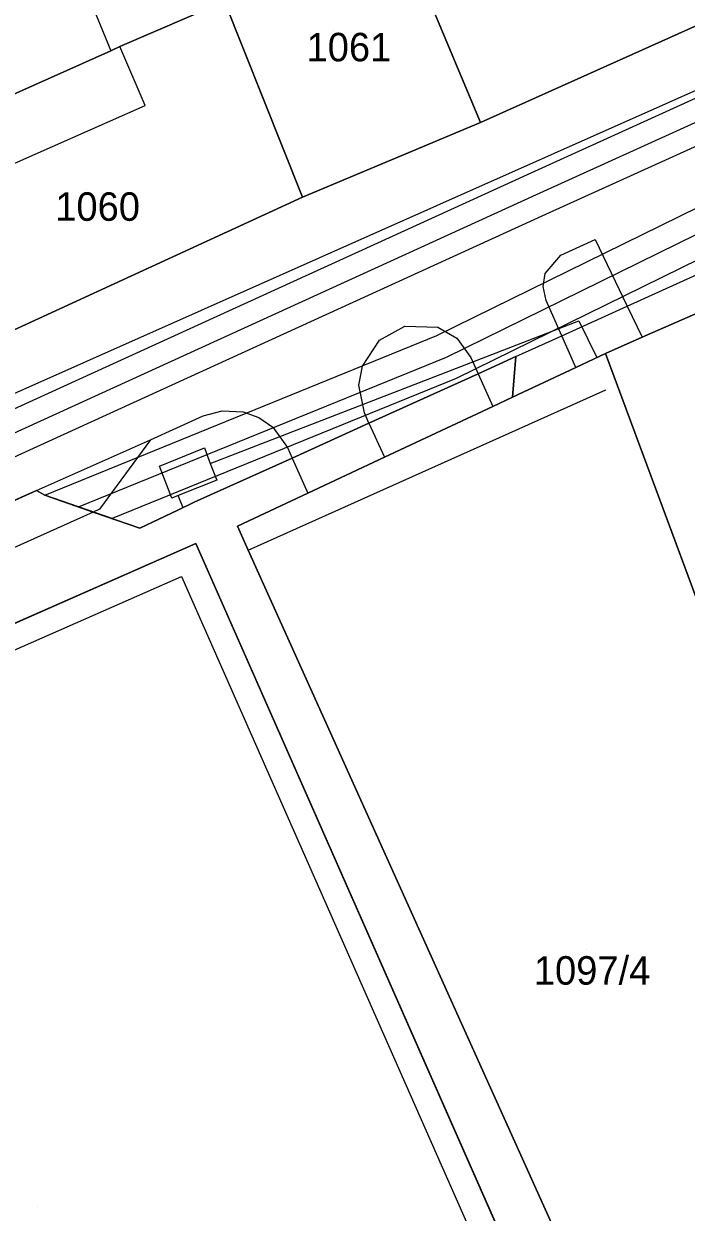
# Model space of a CAD drawing. Extents: x -263423 to -261326, y -1240067 to -1237864.
# Drawn here: x -262627.1 to -262580.6, y -1239899.5 to -1239816.1 of the extents above; entities that cross this region are included whole.
import ezdxf

# ---------------------------------------------------------------- set-up
doc = ezdxf.new("R2010")
doc.units = 0
for name, color, linetype in [('body_kn', 7, 'Continuous'), ('kladpar_druhypozemkov', 7, 'Continuous'), ('kladpar_hranice', 7, 'Continuous'), ('kladpar_parcelnecisla', 7, 'Continuous'), ('kladpar_plochy', 7, 'Continuous'), ('linie', 7, 'Continuous'), ('tarchy_linie', 7, 'Continuous'), ('zappar_hrandruhpozemk', 7, 'Continuous')]:
    doc.layers.add(name, color=color, linetype=linetype)

msp = doc.modelspace()

# ---------------------------------------------------------------- linework, layer by layer
at = {"layer": 'body_kn'}
for p, q in [((-262620.98, -1239817.98), (-262620.98, -1239817.98)), ((-262620.34, -1239817.67), (-262620.34, -1239817.67)), ((-262618.57, -1239821.82), (-262618.57, -1239821.82)), ((-262595.03, -1239823), (-262595.03, -1239823)), ((-262591.74, -1239826.65), (-262591.74, -1239826.65)), ((-262607.52, -1239828.24), (-262607.52, -1239828.24)), ((-262591.1, -1239828.06), (-262591.1, -1239828.06)), ((-262590.46, -1239829.47), (-262590.46, -1239829.47)), ((-262586.98, -1239831.23), (-262586.98, -1239831.23)), ((-262589.38, -1239832.33), (-262589.38, -1239832.33)), ((-262590.5, -1239833.61), (-262590.5, -1239833.61)), ((-262590.64, -1239834.52), (-262590.64, -1239834.52)), ((-262590.43, -1239835.51), (-262590.43, -1239835.51)), ((-262584.73, -1239835.9), (-262584.73, -1239835.9)), ((-262600.35, -1239837.31), (-262600.35, -1239837.31)), ((-262598.02, -1239837.38), (-262598.02, -1239837.38)), ((-262588.12, -1239836.94), (-262588.12, -1239836.94)), ((-262598.1, -1239837.97), (-262598.1, -1239837.97)), ((-262596.69, -1239838.16), (-262596.69, -1239838.16)), ((-262589.32, -1239837.99), (-262589.32, -1239837.99)), ((-262583.68, -1239838.09), (-262583.68, -1239838.09)), ((-262602.12, -1239838.3), (-262602.12, -1239838.3)), ((-262597.42, -1239839.48), (-262597.42, -1239839.48)), ((-262595.7, -1239839.5), (-262595.7, -1239839.5)), ((-262592.55, -1239839.45), (-262592.55, -1239839.45)), ((-262592.55, -1239839.45), (-262592.55, -1239839.45)), ((-262586.86, -1239839.51), (-262586.86, -1239839.51)), ((-262586.25, -1239839.22), (-262586.25, -1239839.22)), ((-262603.31, -1239840.11), (-262603.31, -1239840.11)), ((-262595.19, -1239840.65), (-262595.19, -1239840.65)), ((-262588.33, -1239840.2), (-262588.33, -1239840.2)), ((-262603.56, -1239841.45), (-262603.56, -1239841.45)), ((-262596.74, -1239840.99), (-262596.74, -1239840.99)), ((-262592.79, -1239842.29), (-262592.79, -1239842.29)), ((-262586.23, -1239841.78), (-262586.23, -1239841.78)), ((-262613.17, -1239843.26), (-262613.17, -1239843.26)), ((-262594.17, -1239842.94), (-262594.17, -1239842.94)), ((-262614.49, -1239843.61), (-262614.49, -1239843.61)), ((-262611.7, -1239843.32), (-262611.7, -1239843.32)), ((-262610.58, -1239843.73), (-262610.58, -1239843.73)), ((-262603.17, -1239843.39), (-262603.17, -1239843.39)), ((-262609.62, -1239844.4), (-262609.62, -1239844.4)), ((-262602.86, -1239844.12), (-262602.86, -1239844.12)), ((-262618.2, -1239845.28), (-262618.2, -1239845.28)), ((-262614.4, -1239845.86), (-262614.4, -1239845.86)), ((-262608.58, -1239845.84), (-262608.58, -1239845.84)), ((-262608.26, -1239846.57), (-262608.26, -1239846.57)), ((-262601.78, -1239846.51), (-262601.78, -1239846.51)), ((-262617.57, -1239847.13), (-262617.57, -1239847.13)), ((-262617.57, -1239847.13), (-262617.57, -1239847.13)), ((-262614, -1239846.96), (-262614, -1239846.96)), ((-262614, -1239846.96), (-262614, -1239846.96)), ((-262613.55, -1239848.13), (-262613.55, -1239848.13)), ((-262626.2, -1239848.86), (-262626.2, -1239848.86)), ((-262626.2, -1239848.86), (-262626.2, -1239848.86)), ((-262607.15, -1239849.03), (-262607.15, -1239849.03)), ((-262625.62, -1239849.18), (-262625.62, -1239849.18)), ((-262625.61, -1239849.18), (-262625.61, -1239849.18)), ((-262625.61, -1239849.18), (-262625.61, -1239849.18)), ((-262616.69, -1239849.38), (-262616.69, -1239849.38)), ((-262616.25, -1239849.2), (-262616.25, -1239849.2)), ((-262615.12, -1239849.67), (-262615.12, -1239849.67)), ((-262623.25, -1239850), (-262623.25, -1239850)), ((-262623.25, -1239850), (-262623.25, -1239850)), ((-262622.23, -1239850.36), (-262622.23, -1239850.36)), ((-262621.77, -1239850.15), (-262621.77, -1239850.15)), ((-262616.27, -1239850.24), (-262616.27, -1239850.24)), ((-262615.91, -1239850.06), (-262615.91, -1239850.06)), ((-262620.89, -1239850.82), (-262620.89, -1239850.82)), ((-262618.95, -1239851.5), (-262618.95, -1239851.5)), ((-262612.09, -1239851.35), (-262612.09, -1239851.35)), ((-262615.02, -1239852.56), (-262615.02, -1239852.56)), ((-262611.33, -1239853.03), (-262611.33, -1239853.03)), ((-262616.02, -1239854.88), (-262616.02, -1239854.88))]:
    msp.add_line(p, q, dxfattribs=at)
at = {"layer": 'kladpar_druhypozemkov'}
for p, q in [((-262605.32, -1239816.51), (-262605.32, -1239816.51)), ((-262622.72, -1239827.71), (-262622.72, -1239827.71)), ((-262587.56, -1239881.07), (-262587.56, -1239881.07)), ((-262626.1, -1239899.1), (-262626.1, -1239899.1))]:
    msp.add_line(p, q, dxfattribs=at)
at = {"layer": 'kladpar_hranice'}
msp.add_line((-262660.83, -1239864.32), (-262626.2, -1239848.86), dxfattribs=at)
for points in [[(-262592.7, -1239781.29), (-262577.3, -1239815.05), (-262595.03, -1239823), (-262601.08, -1239808.52), (-262609.4, -1239788.8), (-262611.8, -1239783.18), (-262605.55, -1239780.34), (-262595.22, -1239775.74), (-262592.7, -1239781.29)], [(-262609.4, -1239788.8), (-262601.08, -1239808.52), (-262595.03, -1239823), (-262607.52, -1239828.24), (-262613.01, -1239814.52), (-262613.32, -1239813.81), (-262620.89, -1239795.82), (-262622.72, -1239791.35), (-262624.67, -1239786.69), (-262613.56, -1239778.91), (-262611.8, -1239783.18), (-262609.4, -1239788.8)], [(-262613.01, -1239814.52), (-262620.34, -1239817.67), (-262620.98, -1239817.98), (-262629.39, -1239821.71), (-262633.16, -1239823.41), (-262640.17, -1239826.56), (-262650.38, -1239830.98), (-262658.67, -1239834.7), (-262659.95, -1239835.27), (-262662.31, -1239836.21), (-262662.12, -1239836.92), (-262663.27, -1239837.29), (-262676.46, -1239841.89), (-262677.6, -1239838.06), (-262677.91, -1239838.12), (-262679.61, -1239832.76), (-262679.23, -1239832.57), (-262680.48, -1239828.04), (-262680.93, -1239828.11), (-262682.63, -1239822.68), (-262682.24, -1239822.49), (-262683.37, -1239818.54), (-262646.46, -1239807.43)], [(-262526.13, -1239812.66), (-262542.45, -1239819.98), (-262563.23, -1239829.13), (-262583.68, -1239838.09), (-262586.25, -1239839.22), (-262588.33, -1239840.2), (-262592.79, -1239842.29), (-262592.55, -1239839.45), (-262595.19, -1239840.65), (-262602.86, -1239844.12), (-262608.26, -1239846.57), (-262615.12, -1239849.67), (-262616.27, -1239850.24), (-262618.95, -1239851.5), (-262622.23, -1239850.36), (-262625.62, -1239849.18), (-262626.2, -1239848.86), (-262660.83, -1239864.32), (-262663.01, -1239867.82), (-262666.09, -1239872.77), (-262672.59, -1239875.61)], [(-262629.39, -1239821.71), (-262620.98, -1239817.98), (-262620.34, -1239817.67), (-262613.01, -1239814.52), (-262607.52, -1239828.24), (-262633.99, -1239840.42), (-262640.17, -1239826.56), (-262633.16, -1239823.41), (-262629.39, -1239821.71)], [(-262671.94, -1239857.45), (-262651.98, -1239848.49), (-262649.81, -1239847.42), (-262633.99, -1239840.42), (-262607.52, -1239828.24), (-262595.03, -1239823), (-262577.3, -1239815.05)], [(-262563.23, -1239829.13), (-262555.99, -1239848.2), (-262552.84, -1239856.88), (-262575.15, -1239864.68), (-262576.62, -1239865.19), (-262577.62, -1239862.51), (-262579.01, -1239858.81), (-262580.14, -1239855.68), (-262586.25, -1239839.22), (-262583.68, -1239838.09), (-262563.23, -1239829.13)], [(-262626.2, -1239848.86), (-262625.62, -1239849.18), (-262622.23, -1239850.36), (-262618.95, -1239851.5), (-262616.27, -1239850.24), (-262615.12, -1239849.67), (-262608.26, -1239846.57), (-262602.86, -1239844.12), (-262595.19, -1239840.65), (-262592.55, -1239839.45), (-262592.79, -1239842.29), (-262594.17, -1239842.94), (-262601.78, -1239846.51), (-262607.15, -1239849.03), (-262612.09, -1239851.35), (-262611.33, -1239853.03), (-262580.64, -1239921.19)], [(-262580.14, -1239855.68), (-262579.01, -1239858.81), (-262577.62, -1239862.51), (-262576.62, -1239865.19), (-262559.82, -1239910.87), (-262559.69, -1239911.12), (-262580.64, -1239921.19), (-262611.33, -1239853.03), (-262612.09, -1239851.35), (-262607.15, -1239849.03), (-262601.78, -1239846.51), (-262594.17, -1239842.94), (-262592.79, -1239842.29), (-262588.33, -1239840.2), (-262586.25, -1239839.22), (-262580.14, -1239855.68)], [(-262668.71, -1239876.26), (-262615.02, -1239852.56), (-262584.09, -1239922.71), (-262637.77, -1239946.39), (-262668.71, -1239876.26)], [(-262637.77, -1239946.39), (-262584.09, -1239922.71), (-262615.02, -1239852.56), (-262668.71, -1239876.26), (-262637.77, -1239946.39)]]:
    msp.add_lwpolyline(points, dxfattribs=at)
at = {"layer": 'kladpar_plochy'}
for p, q in [((-262595.19, -1239840.65), (-262592.55, -1239839.45)), ((-262592.55, -1239839.45), (-262592.79, -1239842.29)), ((-262602.86, -1239844.12), (-262595.19, -1239840.65)), ((-262592.79, -1239842.29), (-262594.17, -1239842.94)), ((-262594.17, -1239842.94), (-262601.78, -1239846.51)), ((-262608.26, -1239846.57), (-262602.86, -1239844.12)), ((-262615.12, -1239849.67), (-262608.26, -1239846.57)), ((-262601.78, -1239846.51), (-262607.15, -1239849.03)), ((-262660.83, -1239864.32), (-262626.2, -1239848.86)), ((-262626.2, -1239848.86), (-262625.62, -1239849.18)), ((-262607.15, -1239849.03), (-262612.09, -1239851.35)), ((-262625.62, -1239849.18), (-262622.23, -1239850.36)), ((-262616.27, -1239850.24), (-262615.12, -1239849.67)), ((-262622.23, -1239850.36), (-262618.95, -1239851.5)), ((-262618.95, -1239851.5), (-262616.27, -1239850.24)), ((-262612.09, -1239851.35), (-262611.33, -1239853.03)), ((-262615.02, -1239852.56), (-262668.71, -1239876.26)), ((-262584.09, -1239922.71), (-262615.02, -1239852.56)), ((-262611.33, -1239853.03), (-262580.64, -1239921.19))]:
    msp.add_line(p, q, dxfattribs=at)
for points in [[(-262592.7, -1239781.29), (-262577.3, -1239815.05), (-262595.03, -1239823), (-262601.08, -1239808.52), (-262609.4, -1239788.8), (-262611.8, -1239783.18), (-262605.55, -1239780.34), (-262595.22, -1239775.74)], [(-262609.4, -1239788.8), (-262601.08, -1239808.52), (-262595.03, -1239823), (-262607.52, -1239828.24), (-262613.01, -1239814.52), (-262613.32, -1239813.81), (-262620.89, -1239795.82), (-262622.72, -1239791.35), (-262624.67, -1239786.69), (-262613.56, -1239778.91), (-262611.8, -1239783.18)], [(-262629.39, -1239821.71), (-262620.98, -1239817.98), (-262620.34, -1239817.67), (-262613.01, -1239814.52), (-262607.52, -1239828.24), (-262633.99, -1239840.42), (-262640.17, -1239826.56), (-262633.16, -1239823.41)], [(-262563.23, -1239829.13), (-262555.99, -1239848.2), (-262552.84, -1239856.88), (-262575.15, -1239864.68), (-262576.62, -1239865.19), (-262577.62, -1239862.51), (-262579.01, -1239858.81), (-262580.14, -1239855.68), (-262586.25, -1239839.22), (-262583.68, -1239838.09)], [(-262580.14, -1239855.68), (-262579.01, -1239858.81), (-262577.62, -1239862.51), (-262576.62, -1239865.19), (-262559.82, -1239910.87), (-262559.69, -1239911.12), (-262580.64, -1239921.19), (-262611.33, -1239853.03), (-262612.09, -1239851.35), (-262607.15, -1239849.03), (-262601.78, -1239846.51), (-262594.17, -1239842.94), (-262592.79, -1239842.29), (-262588.33, -1239840.2), (-262586.25, -1239839.22)], [(-262668.71, -1239876.26), (-262615.02, -1239852.56), (-262584.09, -1239922.71), (-262637.77, -1239946.39)]]:
    msp.add_lwpolyline(points, close=True, dxfattribs=at)
for points in [[(-262613.01, -1239814.52), (-262620.34, -1239817.67), (-262620.98, -1239817.98), (-262629.39, -1239821.71), (-262633.16, -1239823.41), (-262640.17, -1239826.56), (-262650.38, -1239830.98), (-262658.67, -1239834.7), (-262659.95, -1239835.27), (-262662.31, -1239836.21), (-262662.12, -1239836.92), (-262663.27, -1239837.29), (-262676.46, -1239841.89), (-262677.6, -1239838.06), (-262677.91, -1239838.12), (-262679.61, -1239832.76), (-262679.23, -1239832.57), (-262680.48, -1239828.04), (-262680.93, -1239828.11), (-262682.63, -1239822.68), (-262682.24, -1239822.49), (-262683.37, -1239818.54), (-262646.46, -1239807.43)], [(-262526.13, -1239812.66), (-262542.45, -1239819.98), (-262563.23, -1239829.13), (-262583.68, -1239838.09), (-262586.25, -1239839.22), (-262588.33, -1239840.2), (-262592.79, -1239842.29), (-262592.55, -1239839.45), (-262595.19, -1239840.65), (-262602.86, -1239844.12), (-262608.26, -1239846.57), (-262615.12, -1239849.67), (-262616.27, -1239850.24), (-262618.95, -1239851.5), (-262622.23, -1239850.36), (-262625.62, -1239849.18), (-262626.2, -1239848.86), (-262660.83, -1239864.32), (-262663.01, -1239867.82), (-262666.09, -1239872.77), (-262672.59, -1239875.61)], [(-262671.94, -1239857.45), (-262651.98, -1239848.49), (-262649.81, -1239847.42), (-262633.99, -1239840.42), (-262607.52, -1239828.24), (-262595.03, -1239823), (-262577.3, -1239815.05)]]:
    msp.add_lwpolyline(points, dxfattribs=at)
at = {"layer": 'linie'}
msp.add_lwpolyline([(-262521.46, -1239790.07), (-262540.33, -1239798.65), (-262560.41, -1239807.74), (-262562.89, -1239808.81), (-262563.41, -1239809.03), (-262572.52, -1239812.91), (-262575.06, -1239814.02), (-262575.26, -1239814.11), (-262577.3, -1239815.05), (-262595.03, -1239823), (-262607.52, -1239828.24), (-262633.99, -1239840.42), (-262649.81, -1239847.42), (-262651.98, -1239848.49), (-262671.94, -1239857.45), (-262714.44, -1239876.51), (-262740.08, -1239884.8)], dxfattribs=at)
at = {"layer": 'tarchy_linie'}
msp.add_line((-262615.91, -1239850.06), (-262616.25, -1239849.2), dxfattribs=at)
for points in [[(-262673.94, -1239865.89), (-262591.1, -1239828.06), (-262563.05, -1239815.33), (-262497.85, -1239786.86), (-262417.23, -1239749.97)], [(-262625.61, -1239849.18), (-262598.1, -1239837.97), (-262552.16, -1239815.39), (-262503.39, -1239793.76), (-262454.87, -1239772.05), (-262415.39, -1239754.52), (-262414.77, -1239756.05), (-262414.15, -1239757.58), (-262453.53, -1239775.07), (-262502.05, -1239796.78), (-262550.76, -1239818.39), (-262596.74, -1239840.99), (-262620.89, -1239850.82), (-262623.25, -1239850), (-262625.61, -1239849.18)], [(-262623.25, -1239850), (-262597.42, -1239839.48), (-262551.46, -1239816.89), (-262502.72, -1239795.27), (-262454.2, -1239773.56), (-262414.77, -1239756.05)], [(-262497.22, -1239788.28), (-262562.42, -1239816.75), (-262590.46, -1239829.47), (-262673.55, -1239867.41), (-262673.55, -1239867.4), (-262673.94, -1239865.89), (-262674.34, -1239864.37), (-262591.74, -1239826.65), (-262565.09, -1239814.55)], [(-262614, -1239846.96), (-262588.12, -1239836.94), (-262586.86, -1239839.51)], [(-262617.57, -1239847.13), (-262614.4, -1239845.86), (-262614, -1239846.96), (-262613.55, -1239848.13), (-262616.25, -1239849.2), (-262616.69, -1239849.38), (-262617.57, -1239847.13)]]:
    msp.add_lwpolyline(points, dxfattribs=at)
at = {"layer": 'zappar_hrandruhpozemk'}
for p, q in [((-262618.57, -1239821.82), (-262620.34, -1239817.67)), ((-262631.26, -1239827.43), (-262618.57, -1239821.82)), ((-262589.38, -1239832.33), (-262586.98, -1239831.23)), ((-262602.12, -1239838.3), (-262600.35, -1239837.31)), ((-262592.55, -1239839.45), (-262589.32, -1239837.99)), ((-262588.33, -1239840.2), (-262589.32, -1239837.99)), ((-262595.19, -1239840.65), (-262594.17, -1239842.94)), ((-262611.33, -1239853.03), (-262586.23, -1239841.78)), ((-262613.17, -1239843.26), (-262611.7, -1239843.32)), ((-262602.86, -1239844.12), (-262601.78, -1239846.51)), ((-262626.2, -1239848.86), (-262618.2, -1239845.28)), ((-262618.2, -1239845.28), (-262621.77, -1239850.15)), ((-262608.26, -1239846.57), (-262607.15, -1239849.03)), ((-262622.23, -1239850.36), (-262661.23, -1239867.89)), ((-262621.77, -1239850.15), (-262622.23, -1239850.36)), ((-262666.51, -1239877.16), (-262616.02, -1239854.88)), ((-262616.02, -1239854.88), (-262586.5, -1239921.76))]:
    msp.add_line(p, q, dxfattribs=at)
for points in [[(-262589.32, -1239837.99), (-262584.73, -1239835.9), (-262508.6, -1239801.39)], [(-262668.1, -1239821.15), (-262642.86, -1239813.62), (-262625.96, -1239805.8), (-262620.98, -1239817.98)], [(-262672.03, -1239861.72), (-262573.53, -1239817.9), (-262572.34, -1239817.05)], [(-262586.98, -1239831.23), (-262584.73, -1239835.9), (-262583.68, -1239838.09)], [(-262589.32, -1239837.99), (-262590.43, -1239835.51), (-262590.64, -1239834.52), (-262590.5, -1239833.61), (-262589.38, -1239832.33)], [(-262600.35, -1239837.31), (-262598.02, -1239837.38), (-262596.69, -1239838.16), (-262595.7, -1239839.5), (-262595.19, -1239840.65)], [(-262602.86, -1239844.12), (-262603.17, -1239843.39), (-262603.56, -1239841.45), (-262603.31, -1239840.11), (-262602.12, -1239838.3)], [(-262618.2, -1239845.28), (-262614.49, -1239843.61), (-262613.17, -1239843.26)], [(-262611.7, -1239843.32), (-262610.58, -1239843.73), (-262609.62, -1239844.4), (-262608.58, -1239845.84), (-262608.26, -1239846.57)]]:
    msp.add_lwpolyline(points, dxfattribs=at)

# ---------------------------------------------------------------- texts
at = {"layer": 'kladpar_parcelnecisla'}
for s, p in [('1061', (-262607.243, -1239818.71)), ('1060', (-262624.883, -1239829.91)), ('1097/4', (-262591.285, -1239883.55))]:
    msp.add_text(s, height=2, dxfattribs=at).set_placement(p)

doc.saveas('drawing.dxf')
